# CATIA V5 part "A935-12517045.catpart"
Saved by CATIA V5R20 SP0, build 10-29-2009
Part number: A935-12517045
Source: Unknown
Property "A": "85.000"
Property "ARTICLENO": "A935-12517045"
Property "B": "20.000"
Property "BOMINFO": "A935-12517045"
Property "CODE": "A935-12517045"
Property "L": "170.000"
Property "L1": "143.370"
Property "LINA": "A935-12517045"
Property "NB": "A935-12517045"
Property "NBSYN": "$CODE."
Property "NN": "A935"
Property "NT": "VDI 3357 H-Type Cam Drivers, steel (16MnCr5)"
Property "SUPPLIER": "CF"
Property "T": "45.000"
Property "W": "125.000"
Bounding box of the stored display mesh (mm): x 0 to 170, y 0 to 45, z -125 to 0
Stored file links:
  C:\Users\Utente\Desktop\3D files A935\A935-12517045.catpart
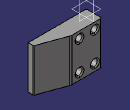
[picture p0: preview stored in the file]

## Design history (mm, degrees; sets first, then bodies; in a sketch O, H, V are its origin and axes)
Body1 "Geometry.1" (main body)
  Solid1 "A935-12517045.catpart": solid without history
